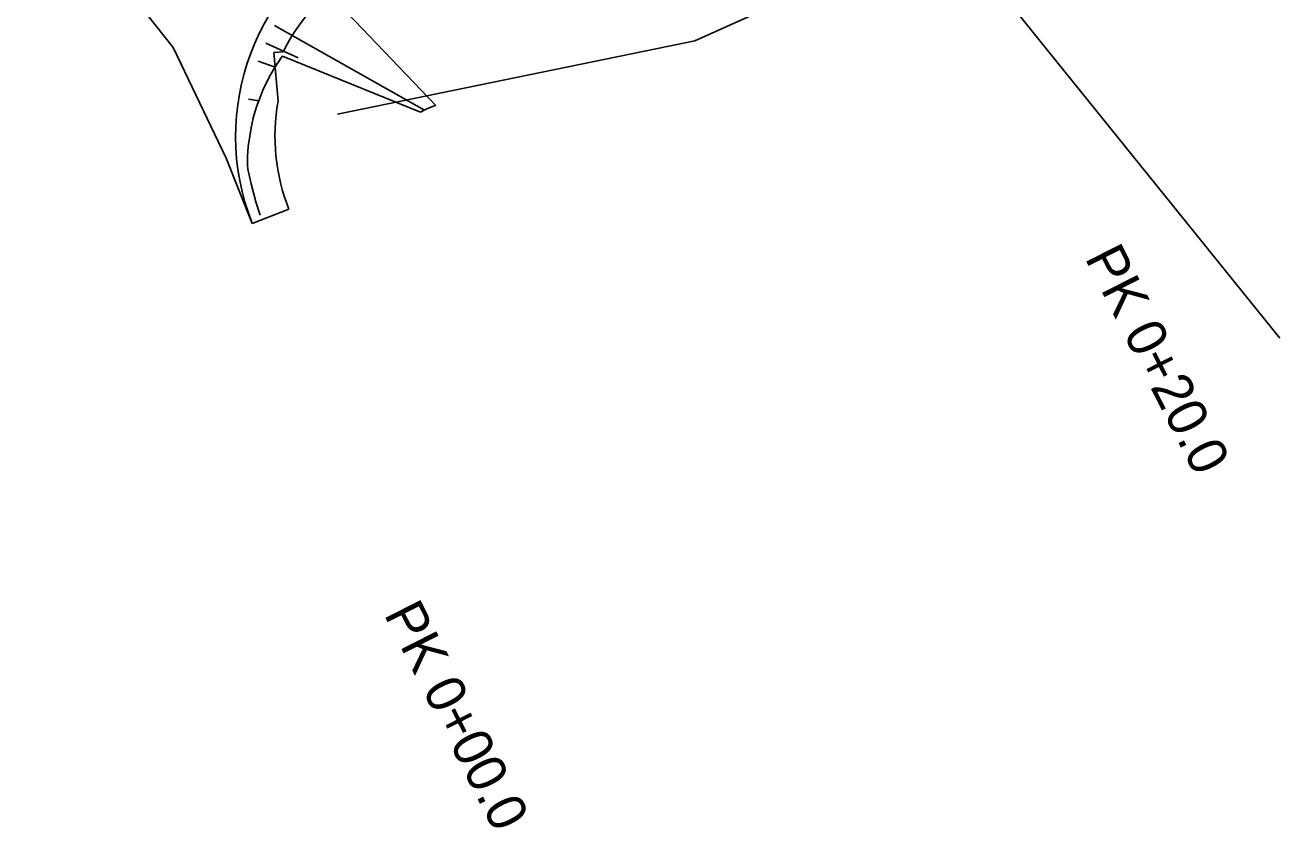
# Model space of a CAD drawing. Extents: x 554247.5 to 554326.1, y 6593477.6 to 6593537.1.
# Drawn here: x 554257.45 to 554289.37, y 6593477.65 to 6593498.07 of the extents above; entities that cross this region are included whole.
import ezdxf

# ---------------------------------------------------------------- set-up
doc = ezdxf.new("R2010")
doc.units = 0
for name, color, linetype in [('ASF', 7, 'Continuous'), ('FILL ASF KT', 7, 'Continuous'), ('FILL ROHELINE', 7, 'Continuous'), ('KRAAV PUHASTAMINE', 7, 'Continuous'), ('NÕLV', 7, 'Continuous'), ('PK', 7, 'Continuous')]:
    doc.layers.add(name, color=color, linetype=linetype)

msp = doc.modelspace()

# ---------------------------------------------------------------- linework, layer by layer
at = {"layer": 'ASF'}
msp.add_lwpolyline([(554263.226, 6593493.02), (554262.564, 6593494.685), (554261.213, 6593497.498), (554259.482, 6593499.687), (554257.446, 6593501.567), (554257.556, 6593501.544)], dxfattribs=at)
msp.add_arc((554268.802, 6593495.236), 6, 116.9456, 201.6745, dxfattribs=at)
at = {"layer": 'FILL ASF KT'}
msp.add_lwpolyline([(554257.556, 6593501.544), (554257.446, 6593501.567), (554259.482, 6593499.687), (554261.213, 6593497.498), (554262.564, 6593494.685), (554263.226, 6593493.02)], dxfattribs=at)
msp.add_arc((554268.802, 6593495.236), 6, 116.9456, 201.6745, dxfattribs=at)
at = {"layer": 'FILL ROHELINE'}
msp.add_line((554263.226, 6593493.02), (554264.155, 6593493.389), dxfattribs=at)
for points in [[(554264.015, 6593497.388), (554263.776, 6593497.367), (554263.882, 6593496.13)], [(554263.882, 6593496.13), (554263.776, 6593497.367), (554264.015, 6593497.388)], [(554264.155, 6593493.389), (554263.226, 6593493.02)]]:
    msp.add_lwpolyline(points, dxfattribs=at)
for centre, radius, start, end in [((554268.802, 6593495.236), 6, 116.9456, 201.6745), ((554268.802, 6593495.236), 6, 116.9456, 201.6745), ((554268.171, 6593495.373), 4.619, 110.7356, 154.1385), ((554268.171, 6593495.373), 4.619, 110.7356, 154.1385), ((554268.802, 6593495.236), 5, 169.6962, 201.6745), ((554268.802, 6593495.236), 5, 169.6962, 201.6745)]:
    msp.add_arc(centre, radius, start, end, dxfattribs=at)
at = {"layer": 'KRAAV PUHASTAMINE'}
for points in [[(554289.368, 6593490.108), (554278.553, 6593503.507)], [(554279.884, 6593502.023), (554277.072, 6593498.839), (554274.487, 6593497.666), (554265.394, 6593495.804)]]:
    msp.add_lwpolyline(points, dxfattribs=at)
at = {"layer": 'NÕLV'}
for p, q in [((554263.792, 6593498.057), (554267.608, 6593495.908)), ((554263.567, 6593497.611), (554264.392, 6593497.236)), ((554263.379, 6593497.148), (554263.805, 6593496.997)), ((554263.133, 6593496.18), (554263.39, 6593496.137))]:
    msp.add_line(p, q, dxfattribs=at)
msp.add_lwpolyline([(554263.423, 6593493.231), (554263.312, 6593493.568), (554263.193, 6593494.031), (554263.116, 6593494.407), (554263.104, 6593494.501), (554263.108, 6593494.733), (554263.124, 6593494.98), (554263.193, 6593495.451), (554263.221, 6593495.582), (554263.25, 6593495.702), (554263.251, 6593495.705), (554263.252, 6593495.707), (554263.309, 6593495.908), (554263.334, 6593495.989), (554263.468, 6593496.345), (554263.498, 6593496.416), (554263.665, 6593496.759), (554263.675, 6593496.778), (554263.724, 6593496.864), (554263.784, 6593496.964), (554263.786, 6593496.967), (554263.787, 6593496.969), (554263.869, 6593497.098), (554263.901, 6593497.146), (554263.955, 6593497.225), (554263.992, 6593497.276), (554267.503, 6593495.856), (554267.517, 6593495.863), (554267.518, 6593495.864), (554267.601, 6593495.905), (554267.646, 6593495.926), (554267.767, 6593495.977), (554267.88, 6593496.02), (554267.894, 6593496.025), (554264.889, 6593499.172)], dxfattribs=at)

# ---------------------------------------------------------------- texts
at = {"layer": 'PK'}
for s, p in [('PK 0+20.0', (554284.392, 6593492.15)), ('PK 0+00.0', (554266.563, 6593483.087))]:
    msp.add_text(s, height=1, rotation=296.9456, dxfattribs=at).set_placement(p)

doc.saveas('drawing.dxf')
